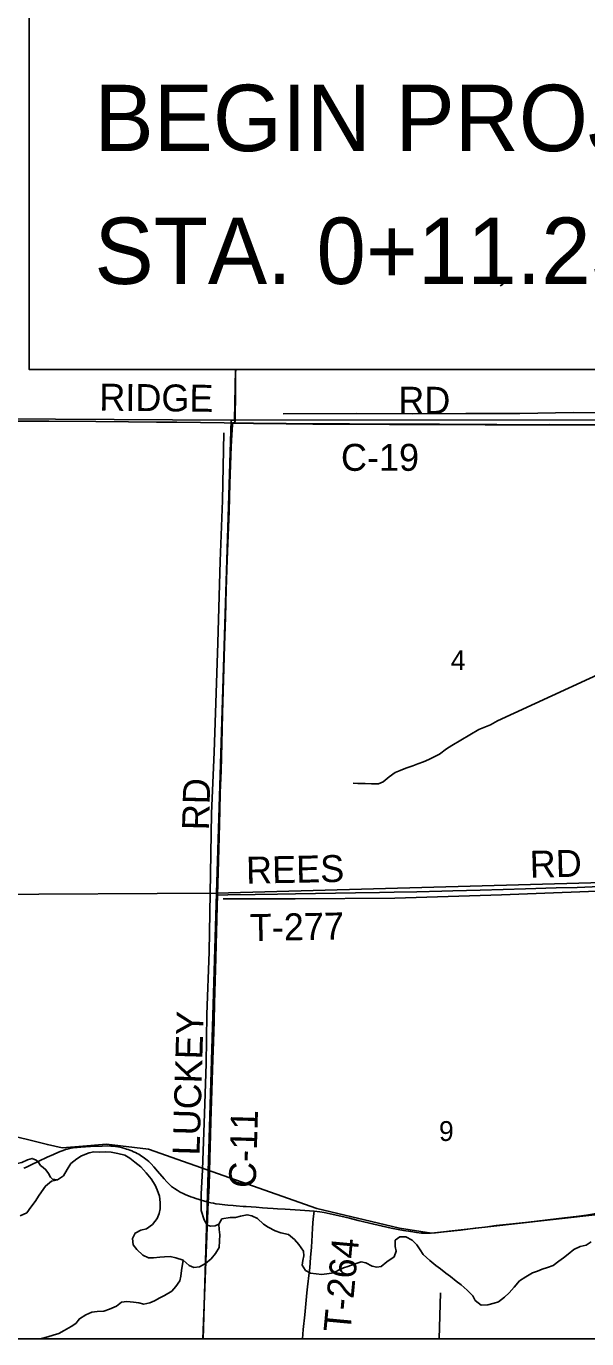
# Model space of a CAD drawing. Extents: x 0 to 34, y 0 to 22.
# Drawn here: x 3.037 to 4.218, y 14.1 to 16.867 of the extents above; entities that cross this region are included whole.
import ezdxf

# ---------------------------------------------------------------- set-up
doc = ezdxf.new("R2010")
doc.units = 0
for name, color, linetype in [('GM_X_City_Street', 7, 'Continuous'), ('GM_X_County_Road', 7, 'Continuous'), ('GM_X_County_Road_Text', 7, 'Continuous'), ('GM_X_Major_River', 7, 'Continuous'), ('GM_X_Minor_Lake', 7, 'Continuous'), ('GM_X_Minor_River', 7, 'Continuous'), ('GM_X_Rail_Line', 7, 'Continuous'), ('GM_X_Section', 7, 'Continuous'), ('GM_X_Section_Text', 7, 'Continuous'), ('GM_X_State_Route', 7, 'Continuous'), ('GM_X_Township_Road', 7, 'Continuous'), ('GM_X_Township_Road_Text', 7, 'Continuous'), ('GM_X_US_Route', 7, 'Continuous'), ('SH_Cut_Line', 7, 'Continuous'), ('SH_Data', 7, 'Continuous'), ('SH_Text', 7, 'Continuous')]:
    doc.layers.add(name, color=color, linetype=linetype)

msp = doc.modelspace()

# ---------------------------------------------------------------- linework, layer by layer
at = {"layer": 'GM_X_City_Street'}
for points in [[(3.4093, 14.1), (4.4112, 14.1), (4.4299, 15.0671), (3.4378, 15.0391)], [(2.4083, 14.1), (3.4093, 14.1), (3.4378, 15.0391), (2.4374, 15.0335)]]:
    msp.add_lwpolyline(points, close=True, dxfattribs=at)
at = {"layer": 'GM_X_County_Road'}
msp.add_line((3.4718, 16.0303), (3.4764, 16.0302), dxfattribs=at)
for points in [[(3.4764, 16.0302), (3.4765, 16.0367), (3.4766, 16.0418), (3.4768, 16.0512), (3.4775, 16.0823), (3.4778, 16.1351), (3.4779, 16.1435)], [(2.9693, 16.0348), (2.9813, 16.0347), (3.0341, 16.0344), (3.0838, 16.0342), (3.1833, 16.0334), (3.2517, 16.0331), (3.3107, 16.0325), (3.3542, 16.0321), (3.404, 16.0314), (3.4537, 16.0307), (3.4718, 16.0303)], [(3.4396, 15.0351), (3.4409, 15.0831), (3.4429, 15.1576), (3.4445, 15.2136), (3.4455, 15.2508), (3.447, 15.2974), (3.4494, 15.3844), (3.4502, 15.4186), (3.4518, 15.4652), (3.4546, 15.5615), (3.4564, 15.6205), (3.458, 15.6795), (3.4603, 15.7419), (3.4616, 15.7771), (3.464, 15.8442), (3.4658, 15.9032), (3.4685, 15.9809), (3.4695, 16.0057), (3.4705, 16.0156), (3.4715, 16.0265), (3.4718, 16.0303)], [(3.4764, 16.0302), (3.4941, 16.0299), (3.5158, 16.0296), (3.5842, 16.029), (3.6402, 16.0284), (3.7179, 16.028), (3.7552, 16.0278), (3.8018, 16.0277), (3.8671, 16.0272), (3.9075, 16.0272), (4.0038, 16.0267), (4.0287, 16.0268), (4.0753, 16.0265), (4.1406, 16.0266), (4.2618, 16.0262), (4.3115, 16.026), (4.3613, 16.0257), (4.4141, 16.0255), (4.4524, 16.0253)], [(3.4201, 14.3879), (3.4206, 14.3965), (3.4208, 14.3996), (3.4217, 14.4214), (3.4235, 14.4804), (3.4249, 14.5301), (3.4258, 14.5581), (3.4273, 14.6016), (3.4301, 14.6885), (3.4313, 14.7258), (3.4323, 14.7693), (3.4333, 14.8066), (3.4361, 14.9029), (3.439, 15.0116), (3.4396, 15.0351)]]:
    msp.add_lwpolyline(points, dxfattribs=at)
at = {"layer": 'GM_X_Major_River'}
for points in [[(3.426, 14.2687), (3.414, 14.2584), (3.4017, 14.2518), (3.39, 14.2502), (3.3802, 14.2543), (3.3669, 14.2656), (3.3521, 14.2707), (3.3398, 14.2731), (3.3276, 14.2726), (3.3178, 14.2717), (3.3045, 14.2709), (3.2939, 14.2708), (3.2819, 14.2764), (3.2693, 14.2881), (3.262, 14.2981), (3.2606, 14.3113), (3.266, 14.3227), (3.2779, 14.3292), (3.2901, 14.332), (3.3025, 14.3411), (3.3122, 14.3538), (3.317, 14.3639), (3.3188, 14.3738), (3.3191, 14.387), (3.3172, 14.4008), (3.3126, 14.4142), (3.3083, 14.4237), (3.2999, 14.4369), (3.2896, 14.4496), (3.2782, 14.4624), (3.2656, 14.4722), (3.2548, 14.4808), (3.2443, 14.4868), (3.2297, 14.4905), (3.2153, 14.4935), (3.2029, 14.4942), (3.1907, 14.493), (3.179, 14.494), (3.1691, 14.492), (3.153, 14.4856), (3.1434, 14.4793), (3.1307, 14.4694), (3.1228, 14.4571), (3.1149, 14.4436), (3.1022, 14.4352), (3.09, 14.4324), (3.0769, 14.4217), (3.0636, 14.4026)], [(3.0636, 14.4026), (3.055, 14.3891), (3.0464, 14.3775), (3.0375, 14.3655), (3.024, 14.3589)], [(4.2271, 14.3044), (4.2167, 14.2974), (4.2037, 14.2947), (4.1907, 14.2885), (4.1787, 14.2786), (4.1691, 14.2705), (4.1594, 14.2635), (4.1471, 14.2547), (4.1352, 14.2504), (4.1241, 14.2465), (4.1138, 14.2426), (4.1035, 14.239), (4.0897, 14.2306), (4.0762, 14.2219), (4.0649, 14.2085), (4.0544, 14.1966), (4.0443, 14.1877), (4.0319, 14.1781), (4.0224, 14.1753), (4.0094, 14.1715), (3.9954, 14.1711), (3.9828, 14.1809), (3.9777, 14.1905), (3.9659, 14.2025), (3.9533, 14.2138), (3.9429, 14.2217), (3.931, 14.2314), (3.9206, 14.2381), (3.9095, 14.2475), (3.8998, 14.2542), (3.8868, 14.2648), (3.8731, 14.2776), (3.8669, 14.2873), (3.86, 14.2981), (3.8496, 14.3078), (3.8369, 14.3149), (3.824, 14.3152), (3.8144, 14.3075), (3.8144, 14.2946), (3.8161, 14.2843), (3.812, 14.273), (3.7966, 14.262), (3.7846, 14.2524), (3.7751, 14.2512), (3.7653, 14.2529), (3.7522, 14.2601), (3.7421, 14.2622), (3.7275, 14.2572), (3.7145, 14.2522), (3.705, 14.2494), (3.6947, 14.2444), (3.6847, 14.2393), (3.6748, 14.2373), (3.6596, 14.2357), (3.6479, 14.2368), (3.6358, 14.2382), (3.6253, 14.244), (3.6184, 14.2549), (3.6194, 14.2648), (3.6216, 14.275), (3.6207, 14.2845), (3.6108, 14.2984), (3.602, 14.3089), (3.589, 14.3198), (3.5728, 14.3232), (3.5613, 14.3274), (3.5466, 14.3352), (3.5369, 14.3416), (3.5239, 14.3536), (3.5119, 14.3592), (3.5021, 14.3614), (3.4884, 14.3587), (3.4778, 14.3555), (3.4664, 14.3554), (3.4489, 14.3525), (3.4427, 14.3418), (3.4434, 14.3305), (3.4447, 14.3191), (3.444, 14.3062), (3.4429, 14.2926), (3.4357, 14.2795), (3.426, 14.2687)]]:
    msp.add_lwpolyline(points, dxfattribs=at)
at = {"layer": 'GM_X_Minor_Lake'}
for p, q in [((4.1684, 16.7327), (4.1832, 16.735)), ((4.0416, 16.3233), (4.0354, 16.32))]:
    msp.add_line(p, q, dxfattribs=at)
at = {"layer": 'GM_X_Minor_River'}
msp.add_line((3.9093, 14.1971), (3.9069, 14.1), dxfattribs=at)
for points in [[(4.9325, 15.8145), (4.9369, 15.913), (4.9376, 16.0208), (4.9386, 16.0439), (4.9346, 16.0493), (4.9327, 16.0494), (4.9239, 16.0484), (4.713, 16.0482), (4.5203, 16.0499), (4.356, 16.0519), (4.1897, 16.0525), (4.0765, 16.0504), (3.9632, 16.0504), (3.8496, 16.0498), (3.7334, 16.0503), (3.5781, 16.0499)], [(3.4427, 14.3418), (3.435, 14.338), (3.4257, 14.3373), (3.4175, 14.3391), (3.4114, 14.351), (3.405, 14.3702), (3.4051, 14.4047), (3.4083, 14.4559), (3.412, 14.5749), (3.4157, 14.6796), (3.4168, 14.7836), (3.422, 14.9155), (3.4249, 15.0802), (3.4273, 15.2076), (3.4324, 15.3365), (3.4366, 15.4609), (3.44, 15.5671), (3.445, 15.7396), (3.4501, 15.867), (3.4532, 16.0097)], [(4.3385, 15.5446), (4.0301, 15.4025), (4.0151, 15.3945), (3.9906, 15.3841), (3.9334, 15.3506), (3.9226, 15.3436), (3.9076, 15.3326), (3.8964, 15.3268), (3.8849, 15.321), (3.8735, 15.316), (3.8616, 15.3121), (3.8513, 15.3078)], [(3.8513, 15.3078), (3.8364, 15.3028), (3.8245, 15.2982), (3.8138, 15.2935), (3.8011, 15.2843), (3.7887, 15.274), (3.7792, 15.2701), (3.7644, 15.2697), (3.7511, 15.2708), (3.7356, 15.2707), (3.7254, 15.2714)], [(3.4516, 15.0275), (3.6035, 15.0276), (3.8133, 15.029), (4.0384, 15.0357), (4.3129, 15.0465), (4.48, 15.0524), (4.644, 15.0529), (4.8186, 15.0533)], [(3.0668, 14.4649), (3.0615, 14.4732), (3.0571, 14.4767), (3.0492, 14.48), (3.0392, 14.4772), (3.0269, 14.4719), (3.0113, 14.4678), (2.9937, 14.4641), (2.9792, 14.463), (2.9641, 14.4638), (2.9494, 14.4673), (2.9332, 14.4715), (2.9158, 14.4747), (2.886, 14.4801), (2.8255, 14.4898)], [(3.1022, 14.4352), (3.092, 14.4362), (3.0875, 14.4405), (3.0836, 14.4485), (3.0781, 14.4563), (3.0725, 14.4609), (3.0668, 14.4649)], [(3.3669, 14.2656), (3.3637, 14.244), (3.3626, 14.2319), (3.3601, 14.2221), (3.3518, 14.2102), (3.3433, 14.2001), (3.3279, 14.191), (3.3183, 14.1863), (3.3068, 14.1801), (3.2972, 14.1754), (3.2843, 14.1731), (3.2741, 14.1756), (3.2624, 14.1774), (3.2488, 14.1785), (3.2374, 14.1772), (3.227, 14.1688), (3.2121, 14.1623), (3.1998, 14.158), (3.1862, 14.1572), (3.1748, 14.156), (3.1618, 14.1502), (3.1487, 14.1422), (3.1409, 14.1325), (3.1313, 14.1259), (3.1166, 14.1172), (3.1051, 14.1114), (3.0929, 14.1075), (3.0819, 14.104), (3.0655, 14.1)]]:
    msp.add_lwpolyline(points, dxfattribs=at)
at = {"layer": 'GM_X_Rail_Line'}
msp.add_lwpolyline([(2.6869, 14.6075), (3.0811, 14.5095), (3.112, 14.5026), (3.139, 14.5049), (3.2059, 14.5104), (3.2941, 14.4996), (3.6488, 14.3747), (3.8233, 14.3329), (3.8904, 14.3224), (4.141, 14.3508), (4.2603, 14.3642), (4.4109, 14.412), (4.9067, 14.6373)], dxfattribs=at)
at = {"layer": 'GM_X_Section'}
for points in [[(3.4773, 16.1435), (3.4754, 16.0365), (3.4686, 16.0366), (2.4803, 16.0422), (2.4865, 16.4094), (2.4879, 17.0483), (3.4934, 17.0475), (3.4907, 16.8935)], [(4.4803, 16.1435), (4.4786, 16.0375), (4.4532, 16.0374), (3.4754, 16.0365), (3.4773, 16.1435)]]:
    msp.add_lwpolyline(points, dxfattribs=at)
for points in [[(2.4708, 16.042), (2.4803, 16.0422), (3.4686, 16.0366), (3.4378, 15.0391), (2.4374, 15.0335)], [(3.4754, 16.0365), (4.4532, 16.0374), (4.4299, 15.0671), (3.4378, 15.0391), (3.4686, 16.0366)]]:
    msp.add_lwpolyline(points, close=True, dxfattribs=at)
at = {"layer": 'GM_X_State_Route'}
for points in [[(3.0311, 14.4596), (3.0367, 14.4619), (3.0472, 14.4667), (3.0629, 14.4742), (3.0808, 14.4828), (3.0939, 14.4887), (3.1047, 14.4934), (3.1099, 14.4955), (3.1146, 14.4972), (3.119, 14.4988), (3.123, 14.4999), (3.1279, 14.501), (3.1353, 14.5024), (3.144, 14.5035), (3.1514, 14.5042), (3.1719, 14.5052), (3.1968, 14.5062), (3.2068, 14.5064), (3.2149, 14.5063), (3.2195, 14.5061), (3.2243, 14.5056), (3.2292, 14.5048), (3.2335, 14.5039), (3.2396, 14.5025), (3.2441, 14.5013), (3.248, 14.5), (3.2514, 14.4989), (3.2551, 14.4975), (3.2589, 14.496), (3.2629, 14.4942), (3.2667, 14.4924), (3.2704, 14.4904), (3.2735, 14.4888), (3.2764, 14.487), (3.2797, 14.4851), (3.2828, 14.483), (3.2857, 14.4809), (3.2888, 14.4785), (3.2917, 14.4763), (3.2946, 14.4737), (3.3, 14.4685), (3.3056, 14.4626), (3.3132, 14.4535), (3.3269, 14.4374), (3.3327, 14.431), (3.3357, 14.4279), (3.3379, 14.4258), (3.3429, 14.4213), (3.3489, 14.4166), (3.3544, 14.413), (3.3607, 14.4093), (3.3672, 14.4062), (3.3732, 14.4035), (3.3785, 14.4013), (3.3831, 14.3995), (3.388, 14.3977), (3.3942, 14.3955), (3.4008, 14.3933), (3.4072, 14.3913), (3.4152, 14.3891), (3.4201, 14.3879)], [(3.4201, 14.3879), (3.4255, 14.3867), (3.431, 14.3855), (3.4364, 14.3846), (3.4438, 14.3835), (3.4494, 14.3827), (3.4551, 14.3821), (3.4612, 14.3815), (3.4728, 14.3806), (3.4789, 14.38), (3.4938, 14.3791), (3.5, 14.3786), (3.5211, 14.3771), (3.5343, 14.3763), (3.5447, 14.3755), (3.5566, 14.3748), (3.5664, 14.3742), (3.5819, 14.3731), (3.6135, 14.3712), (3.6433, 14.3689), (3.6554, 14.3675), (3.6647, 14.3659), (3.6769, 14.3635), (3.6996, 14.3582), (3.7178, 14.3539), (3.736, 14.3496), (3.7691, 14.3413), (3.7873, 14.3371), (3.8055, 14.3334), (3.8315, 14.3285), (3.8468, 14.3258), (3.8591, 14.324), (3.8698, 14.3228), (3.8791, 14.3223), (3.8884, 14.3225), (3.8992, 14.3233), (3.9177, 14.3252), (3.9517, 14.3291), (3.9825, 14.3328), (4.0041, 14.3355), (4.0273, 14.3384), (4.0551, 14.3415), (4.0953, 14.346), (4.1709, 14.3547), (4.1956, 14.3576), (4.2172, 14.3604), (4.2417, 14.3644)]]:
    msp.add_lwpolyline(points, dxfattribs=at)
at = {"layer": 'GM_X_Township_Road'}
for points in [[(3.4396, 15.0351), (3.4612, 15.0355), (3.5187, 15.0364), (3.5659, 15.0373), (3.6043, 15.0381), (3.6463, 15.0389), (3.7308, 15.0401), (3.7813, 15.0408), (3.8123, 15.0413), (3.8601, 15.0421), (3.9127, 15.0433), (3.9356, 15.044), (3.9934, 15.0457), (4.0419, 15.0474), (4.0888, 15.0485), (4.1537, 15.0503), (4.1979, 15.0516), (4.2458, 15.0533), (4.2762, 15.0541), (4.3791, 15.0582), (4.4278, 15.06), (4.432, 15.0602)], [(3.6327, 14.239), (3.6339, 14.2498), (3.6359, 14.2716), (3.6375, 14.2933), (3.6391, 14.3182), (3.6401, 14.3338), (3.6415, 14.3525), (3.6433, 14.3689)], [(3.6188, 14.1), (3.6204, 14.1195), (3.6234, 14.1506), (3.6267, 14.1816), (3.6282, 14.1971), (3.6295, 14.2095), (3.6327, 14.239)]]:
    msp.add_lwpolyline(points, dxfattribs=at)
at = {"layer": 'GM_X_US_Route'}
for points in [[(2.1, 14.1), (3.4084, 14.1), (3.4199, 14.3884), (3.4204, 14.3971), (3.4205, 14.4002), (3.4214, 14.4219), (3.4233, 14.481), (3.4247, 14.5307), (3.4256, 14.5586), (3.4271, 14.6021), (3.4299, 14.6891), (3.431, 14.7264), (3.4321, 14.7699), (3.4331, 14.8071), (3.4358, 14.9034), (3.4387, 15.0122), (3.4394, 15.0357), (3.4407, 15.0836), (3.4426, 15.1582), (3.4443, 15.2141), (3.4453, 15.2514), (3.4467, 15.298), (3.4492, 15.385), (3.45, 15.4191), (3.4516, 15.4657), (3.4543, 15.562), (3.4562, 15.6211), (3.4578, 15.6801), (3.46, 15.7425), (3.4614, 15.7777), (3.4637, 15.8448), (3.4656, 15.9038), (3.4682, 15.9814), (3.4693, 16.0063), (3.4703, 16.0162), (3.4713, 16.027), (3.4716, 16.0309), (3.4761, 16.0308), (3.4763, 16.0373), (3.4764, 16.0423), (3.4765, 16.0517), (3.4772, 16.0828), (3.4776, 16.1356), (3.4777, 16.1435)], [(3.4777, 16.1435), (3.4776, 16.1356), (3.4772, 16.0828), (3.4765, 16.0517), (3.4764, 16.0423), (3.4763, 16.0373), (3.4761, 16.0308), (3.4939, 16.0304), (3.5156, 16.0302), (3.584, 16.0295), (3.6399, 16.029), (3.7176, 16.0285), (3.755, 16.0284), (3.8016, 16.0283), (3.8668, 16.0278), (3.9072, 16.0278), (4.0036, 16.0273), (4.0285, 16.0273), (4.0751, 16.027), (4.1404, 16.0272), (4.2616, 16.0268)], [(4.2616, 16.0268), (4.1404, 16.0272), (4.0751, 16.027), (4.0285, 16.0273), (4.0036, 16.0273), (3.9072, 16.0278), (3.8668, 16.0278), (3.8016, 16.0283), (3.755, 16.0284), (3.7176, 16.0285), (3.6399, 16.029), (3.584, 16.0295), (3.5156, 16.0302), (3.4939, 16.0304), (3.4761, 16.0308), (3.4716, 16.0309), (3.4713, 16.027), (3.4703, 16.0162), (3.4693, 16.0063), (3.4682, 15.9814), (3.4656, 15.9038), (3.4637, 15.8448), (3.4614, 15.7777), (3.46, 15.7425), (3.4578, 15.6801), (3.4562, 15.6211), (3.4543, 15.562), (3.4516, 15.4657), (3.45, 15.4191), (3.4492, 15.385), (3.4467, 15.298), (3.4453, 15.2514), (3.4443, 15.2141), (3.4426, 15.1582), (3.4407, 15.0836), (3.4394, 15.0357), (3.4387, 15.0122), (3.4358, 14.9034), (3.4331, 14.8071), (3.4321, 14.7699), (3.431, 14.7264), (3.4299, 14.6891), (3.4271, 14.6021), (3.4256, 14.5586), (3.4247, 14.5307), (3.4233, 14.481), (3.4214, 14.4219), (3.4205, 14.4002), (3.4204, 14.3971), (3.4199, 14.3884), (3.4084, 14.1), (7.4244, 14.1)]]:
    msp.add_lwpolyline(points, dxfattribs=at)
at = {"layer": 'SH_Cut_Line'}
msp.add_lwpolyline([(2.1, 20.9), (2.1, 14.1), (7.4244, 14.1)], dxfattribs=at)
at = {"layer": 'SH_Data'}
msp.add_line((2.1, 14.1), (8.9, 14.1), dxfattribs=at)
at = {"layer": 'SH_Text'}
msp.add_lwpolyline([(3.0426, 16.8935), (5.0426, 16.8935), (5.0426, 16.1435), (3.0426, 16.1435)], close=True, dxfattribs=at)

# ---------------------------------------------------------------- texts
at = {"layer": 'GM_X_County_Road_Text'}
for s, rotation, p in [('RIDGE', 359.3517, (3.1902, 16.0567)), ('RD', 0, (3.8206, 16.05)), ('C-19', 0, (3.6998, 15.9297)), ('RD', 88.5117, (3.4216, 15.1714)), ('LUCKEY', 88.3106, (3.4016, 14.4858)), ('C-11', 88.2741, (3.5201, 14.4173))]:
    msp.add_text(s, height=0.05682, rotation=rotation, dxfattribs=at).set_placement(p)
at = {"layer": 'GM_X_Section_Text'}
for s, p in [('4', (3.9314, 15.5097)), ('9', (3.9064, 14.5169))]:
    msp.add_text(s, height=0.0419, rotation=0, dxfattribs=at).set_placement(p)
at = {"layer": 'GM_X_Township_Road_Text'}
for s, rotation, p in [('REES', 1.1238, (3.5003, 15.0592)), ('RD', 1.4825, (4.0984, 15.0716)), ('T-277', 1.1131, (3.5082, 14.9382)), ('T-264', 84.6793, (3.7196, 14.1118))]:
    msp.add_text(s, height=0.05682, rotation=rotation, dxfattribs=at).set_placement(p)
at = {"layer": 'SH_Text'}
for s, p in [('BEGIN PROJECT', (3.1802, 16.6036)), ('STA. 0+11.25', (3.1802, 16.3236))]:
    msp.add_text(s, height=0.14, dxfattribs=at).set_placement(p)

doc.saveas('drawing.dxf')
